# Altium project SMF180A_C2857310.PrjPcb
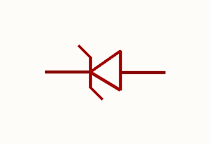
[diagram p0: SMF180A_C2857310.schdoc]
1 sheet, 1 parts. Net scope: global (net labels, ports and power ports of the same name join across sheets).

## Sheet SMF180A_C2857310.schdoc
size 127 x 101 mm

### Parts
D?  smf180a_c2857310  [SMF_L2.8-W1.8-LS3.7-RD]  (value not drawn)

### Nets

Not connected (* = marked no-connect by the designer): D? 1(C) 2(A)

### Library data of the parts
D? = smf180a_c2857310: 极性:单向;反向截止电压(Vrwm):180V;钳位电压:292V;峰值脉冲电流(Ipp):500mA;峰值脉冲功率(Ppp):200W;击穿电压(VBR):201V;; Manufacturer: JSMSEMI(杰盛微); AddInBom: yes; ModelId: d442029593404375a1c1f88df653d02e; ModelName: SMF_L2.8-W1.8-H1.0-LS3.7; ModelTransform: 145.669,70.866,0,180,0,0,0.0005,0,0; Polarity: 单向; Reverse Stand-Off Voltage (Vrwm): 180V; Clamping Voltage: 292V; Peak Pulse Current (Ipp): 500mA; Peak Pulse Power Dissipation (Ppp): 200W; Voltage - Breakdown: 201V; Reverse Leakage Current (Ir): 1uA; Number of Channels: 单路; Type: TVS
